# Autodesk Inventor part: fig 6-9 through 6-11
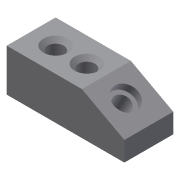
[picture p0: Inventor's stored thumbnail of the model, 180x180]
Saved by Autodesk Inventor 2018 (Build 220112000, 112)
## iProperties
Created: 2009-09
Part Number: fig 6-9 through 6-11
Document SubType Name: Modeling
Designer: Sham
Density: 1 g/cm^3
Material: Generic
Appearance: Default
Author: Sham
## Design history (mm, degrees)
sketch "Sketch1"
  geometry: L1 (-40, 0)-(-40, 12); L2 (-40, 12)-(-14, 26); L3 (-14, 26)-(32.108, 26); L4 (-40, 0)-(32.108, 0); L5 (32.108, 0)-(32.108, 26)
  constraints: 10 end point, 3 perpendicular
extrude "Extrusion1" new body sketch "Sketch1" distance "d0" = 30; taper "d1" = 0 deg
hole "Hole1" diameter "d4" = 10; stored, may be unused: countersink angle "d8" = 90 deg, drill point angle "d10" = 118 deg; dims "d2" = 15, "d3" = 16, "d5" = 6, "d6" = 15, "d7" = 5, "d9" = 12
hole "Hole2" diameter "d13" = 10; stored, may be unused: countersink angle "d17" = 90 deg, drill point angle "d19" = 118 deg; dims "d11" = 12, "d12" = 15, "d14" = 6, "d15" = 15, "d16" = 2, "d18" = 15
hole "Hole3" diameter "d22" = 10; stored, may be unused: countersink angle "d26" = 90 deg, drill point angle "d28" = 118 deg; dims "d20" = 15, "d21" = 15, "d23" = 6, "d24" = 15, "d25" = 2, "d27" = 15
body "Solid1"
